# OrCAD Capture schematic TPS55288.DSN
size D; title: TPS55288 SIMULATION; rev: 1.0
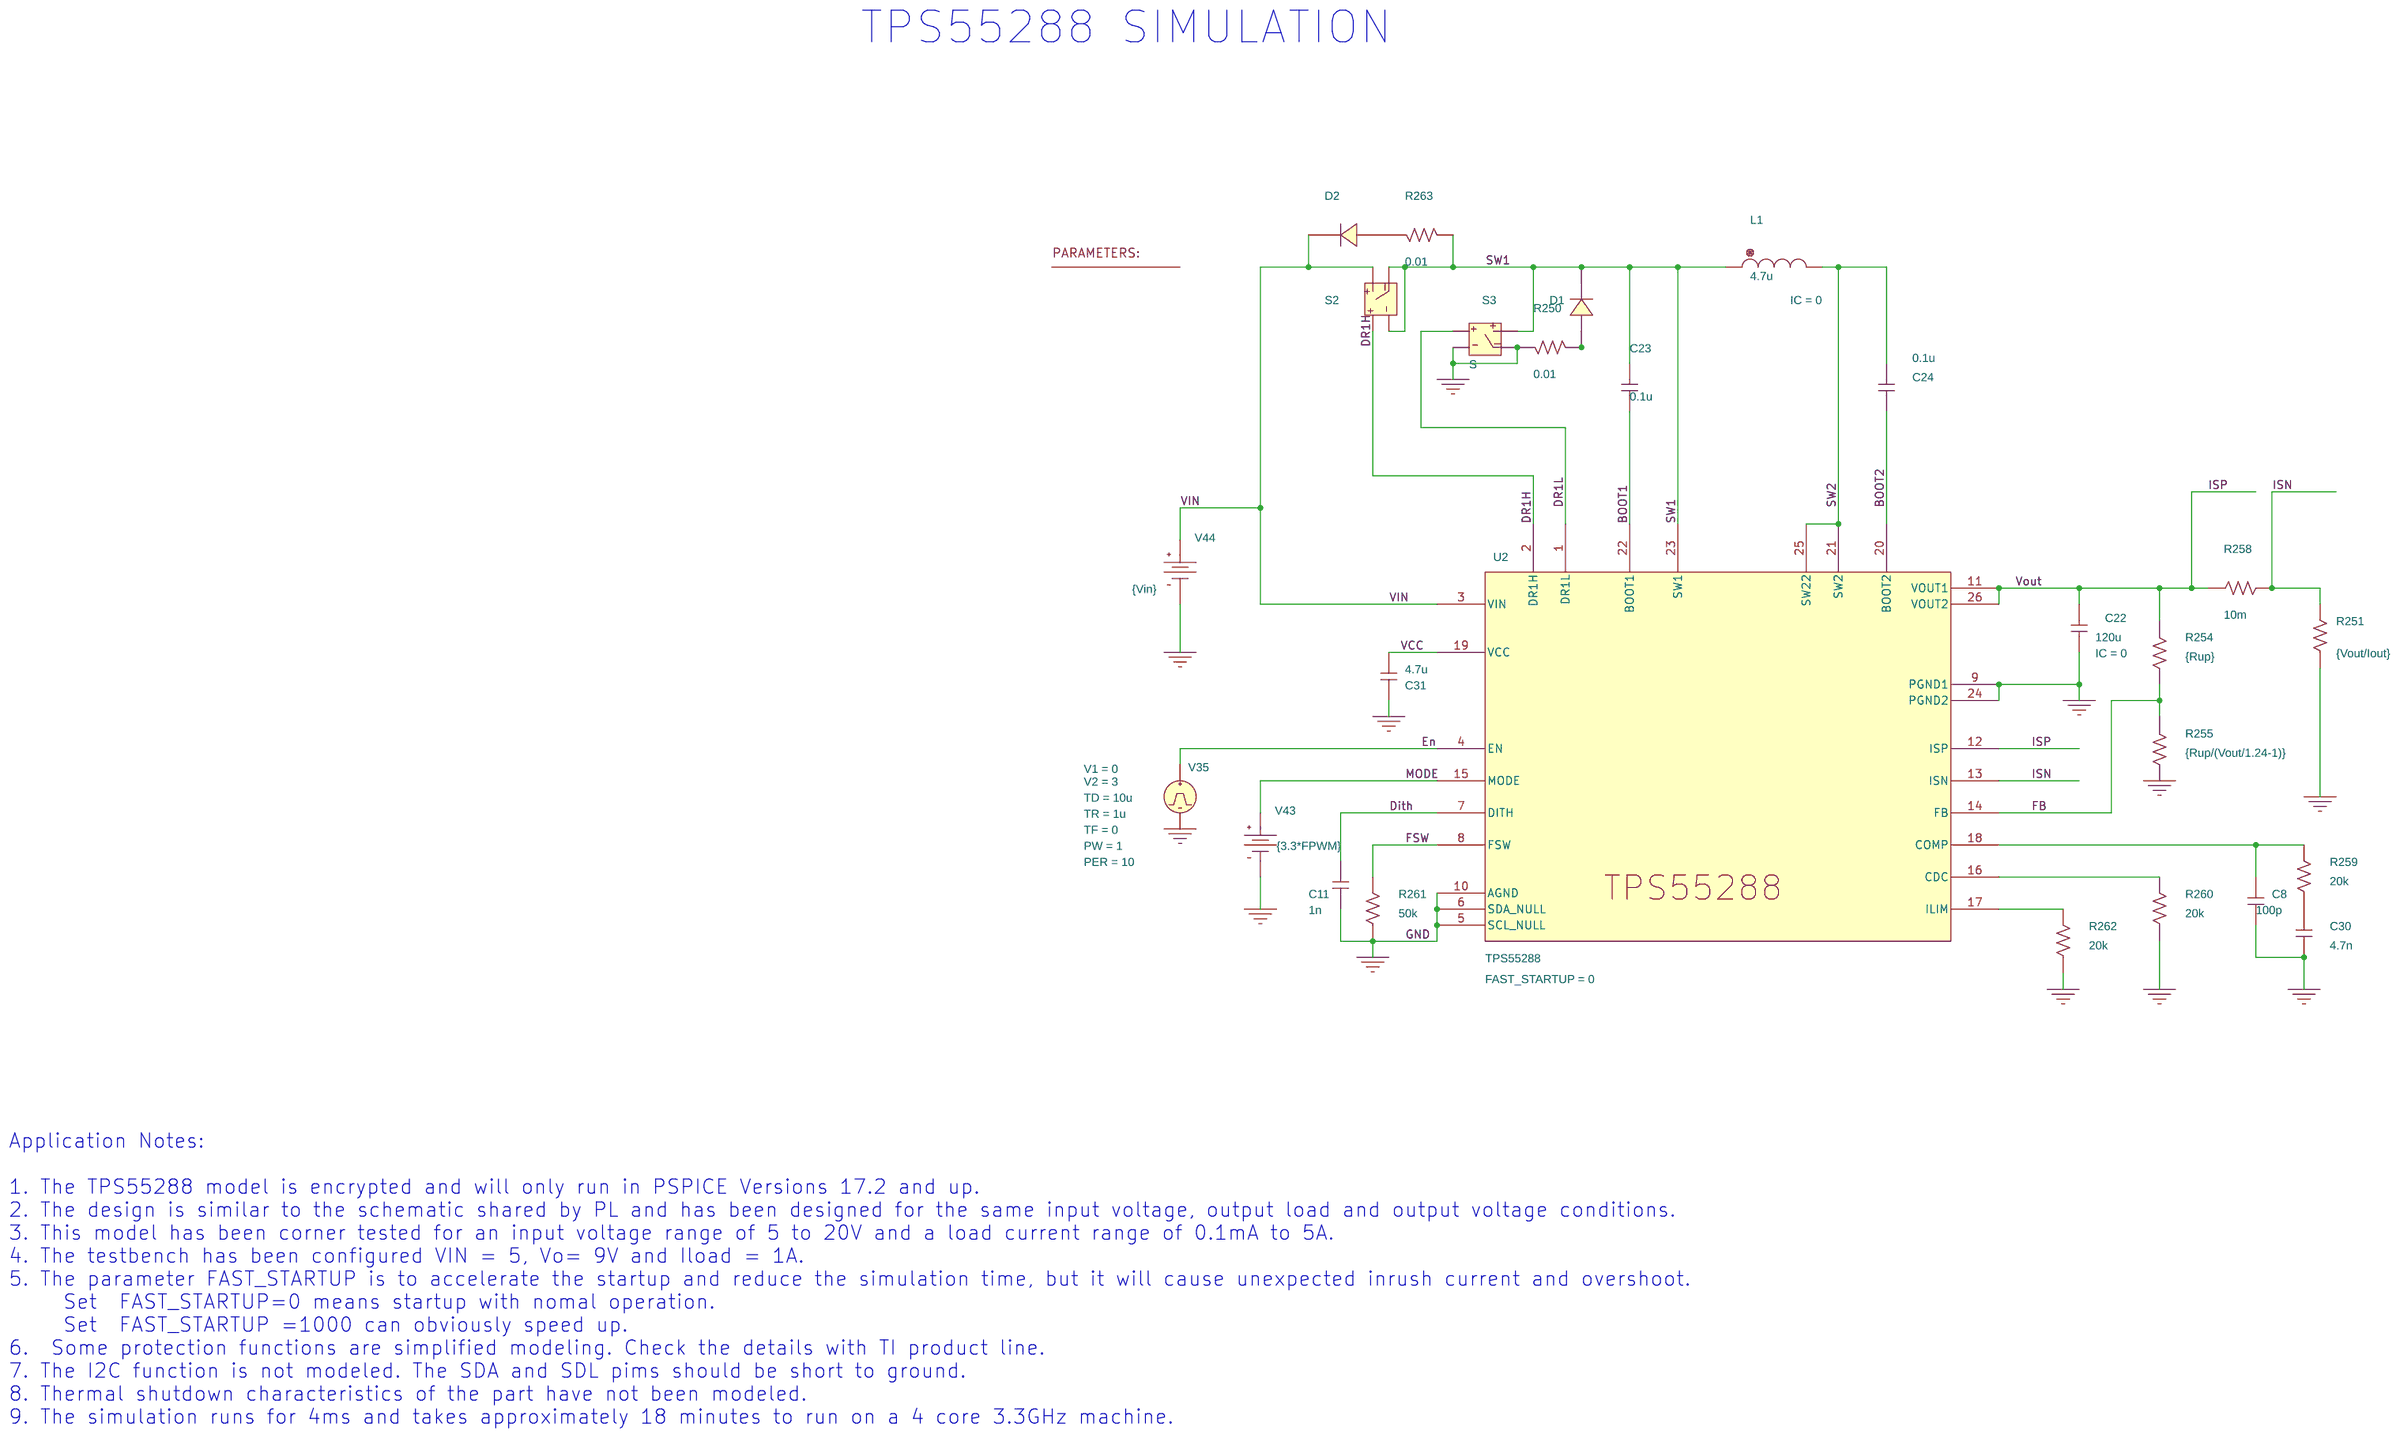
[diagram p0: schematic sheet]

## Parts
1  PARAM
C8  100p  [RAD/CK05]
C11  1n  [RAD/CK05]
C22  120u  [RAD/CK05]
C23  0.1u  [RAD/CK05]
C24  0.1u  [RAD/CK05]
C30  4.7n  [RAD/CK05]
C31  4.7u  [RAD/CK05]
D1  D_D1
D2  D_D1
L1  4.7u  [DISC/.350x.175/LS.200x.100/.034]
R250  0.01  [AX/RC05]
R251  {Vout/Iout}  [AX/RC05]
R254  {Rup}  [AX/RC05]
R255  {Rup/(Vout/1.24-1)}  [AX/RC05]
R258  10m  [AX/RC05]
R259  20k  [AX/RC05]
R260  20k  [AX/RC05]
R261  50k  [AX/RC05]
R262  20k  [AX/RC05]
R263  0.01  [AX/RC05]
S2  S
S3  S
U2  TPS55288
V35  VPULSE
V43  VDC
V44  VDC

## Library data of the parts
1 = PARAM: COUT: 0.75; Fast_Startup: 1000; Rup: 100k; SS: 0; VIN: 5; VOUT: 9
C8 C11 C22-C24 C31 = C: IC: 0
C30 = C
D1 D2 = D_D1
L1 = L: IC: 0
R250 R251 R254 R255 R258-R263 = R
S2 S3 = S: ROFF: 1e9; RON: 18m; VOFF: 0.7; VON: 1.5
U2 = TPS55288_16: FAST_STARTUP: 0
V35 = VPULSE: PER: 10; PW: 1; TD: 10u; TF: 0; TR: 1u; V1: 0; V2: 3
V43 = VDC: DC: {3.3*FPWM}
V44 = VDC: DC: {Vin}

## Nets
VCC: C31.1 U2.19(VCC)
VIN: D2.1(C) S2.2(3) U2.3(VIN) V44.0(+)
0: C8.2 C11.2 C22.2 C30.2 C31.2 R250.1 R251.1 R255.2 R260.1 R261.1 R262.1 S3.1(2) S3.3(4) U2.5(SCL_NULL) U2.6(SDA_NULL) U2.9(PGND1) U2.10(AGND) U2.24(PGND2) V35.2(-) V43.1(-) V44.1(-)
BOOT1: C23.2 U2.22(BOOT1)
BOOT2: C24.2 U2.20(BOOT2)
Dith: C11.1 U2.7(DITH)
DR1H: S2.0(1) U2.2(DR1H)
DR1L: S3.0(1) U2.1(DR1L)
En: U2.4(EN) V35.1(+)
FB: R254.2 R255.1 U2.14(FB)
FSW: R261.2 U2.8(FSW)
ISN: R251.2 R258.2 U2.13(ISN)
ISP: C22.1 R254.1 R258.1 U2.11(VOUT1) U2.12(ISP) U2.26(VOUT2)
MODE: U2.15(MODE) V43.0(+)
SW1: C23.1 D1.1(C) L1.1 R263.2 S2.1(2) S2.3(4) S3.2(3) U2.23(SW1)
SW2: C24.1 L1.2 U2.21(SW2) U2.25(SW22)
N16770235: C8.1 R259.2 U2.18(COMP)
N16798121: D1.2(A) R250.2
N16807735: R262.2 U2.17(ILIM)
N16807737: R260.2 U2.16(CDC)
N16808707: C30.1 R259.1
N16808709: D2.2(A) R263.1

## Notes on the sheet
- TPS55288 SIMULATION
- Application Notes:
  1. The TPS55288 model is encrypted and will only run in PSPICE Versions 17.2 and up.
  2. The design is similar to the schematic shared by PL and has been designed for the same input voltage, output load and output voltage conditions.
  3. This model has been corner tested for an input voltage range of 5 to 20V and a load current range of 0.1mA to 5A.
  4. The testbench has been configured VIN = 5, Vo= 9V and Iload = 1A.
  5. The parameter FAST_STARTUP is to accelerate the startup and reduce the simulation time, but it will cause unexpected inrush current and overshoot.
       Set  FAST_STARTUP=0 means startup with nomal operation.
       Set  FAST_STARTUP =1000 can obviously speed up.
  6.  Some protection functions are simplified modeling. Check the details with TI product line.
  7. The I2C function is not modeled. The SDA and SDL pims should be short to ground.
  8. Thermal shutdown characteristics of the part have not been modeled.
  9. The simulation runs for 4ms and takes approximately 18 minutes to run on a 4 core 3.3GHz machine.
